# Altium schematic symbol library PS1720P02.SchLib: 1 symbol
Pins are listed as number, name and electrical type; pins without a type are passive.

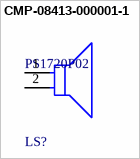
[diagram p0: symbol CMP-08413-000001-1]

## CMP-08413-000001-1
designator LS?, comment PS1720P02
AUDIO PIEZO TRANSDUCER 30V TH; Manufacturer: TDK Corporation; Frequency: 2kHz; Standoff Height: 0.5mm
footprint FP-PS1720P02-MFG
pins: 1, 2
